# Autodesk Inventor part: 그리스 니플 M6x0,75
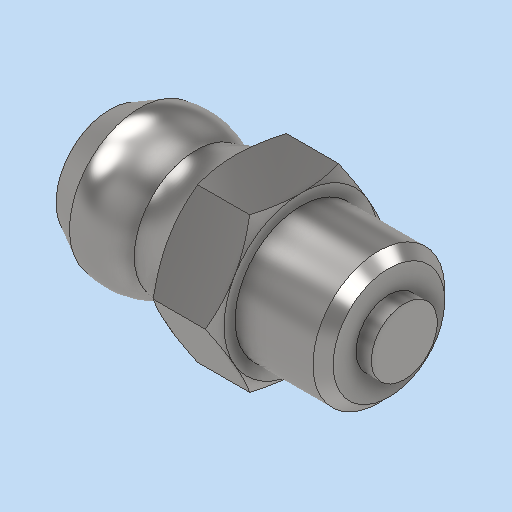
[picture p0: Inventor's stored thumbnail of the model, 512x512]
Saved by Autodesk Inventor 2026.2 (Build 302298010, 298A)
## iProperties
Created: 2026-03
Part Number: 그리스 니플 M6x0,75
Material: 강철, 연강
Description: 윤활 니플, 원추 유형 A
Document SubType Name: Modeling
Designer: PC-2-03
Density: 7.85 g/cm^3
Appearance: 기본값
Author: jhkim
Sending System: Autodesk Inventor 2026
Preprocessor: ST-DEVELOPER v20.1
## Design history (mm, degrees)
feature "Solid1"
node "솔리드1"
